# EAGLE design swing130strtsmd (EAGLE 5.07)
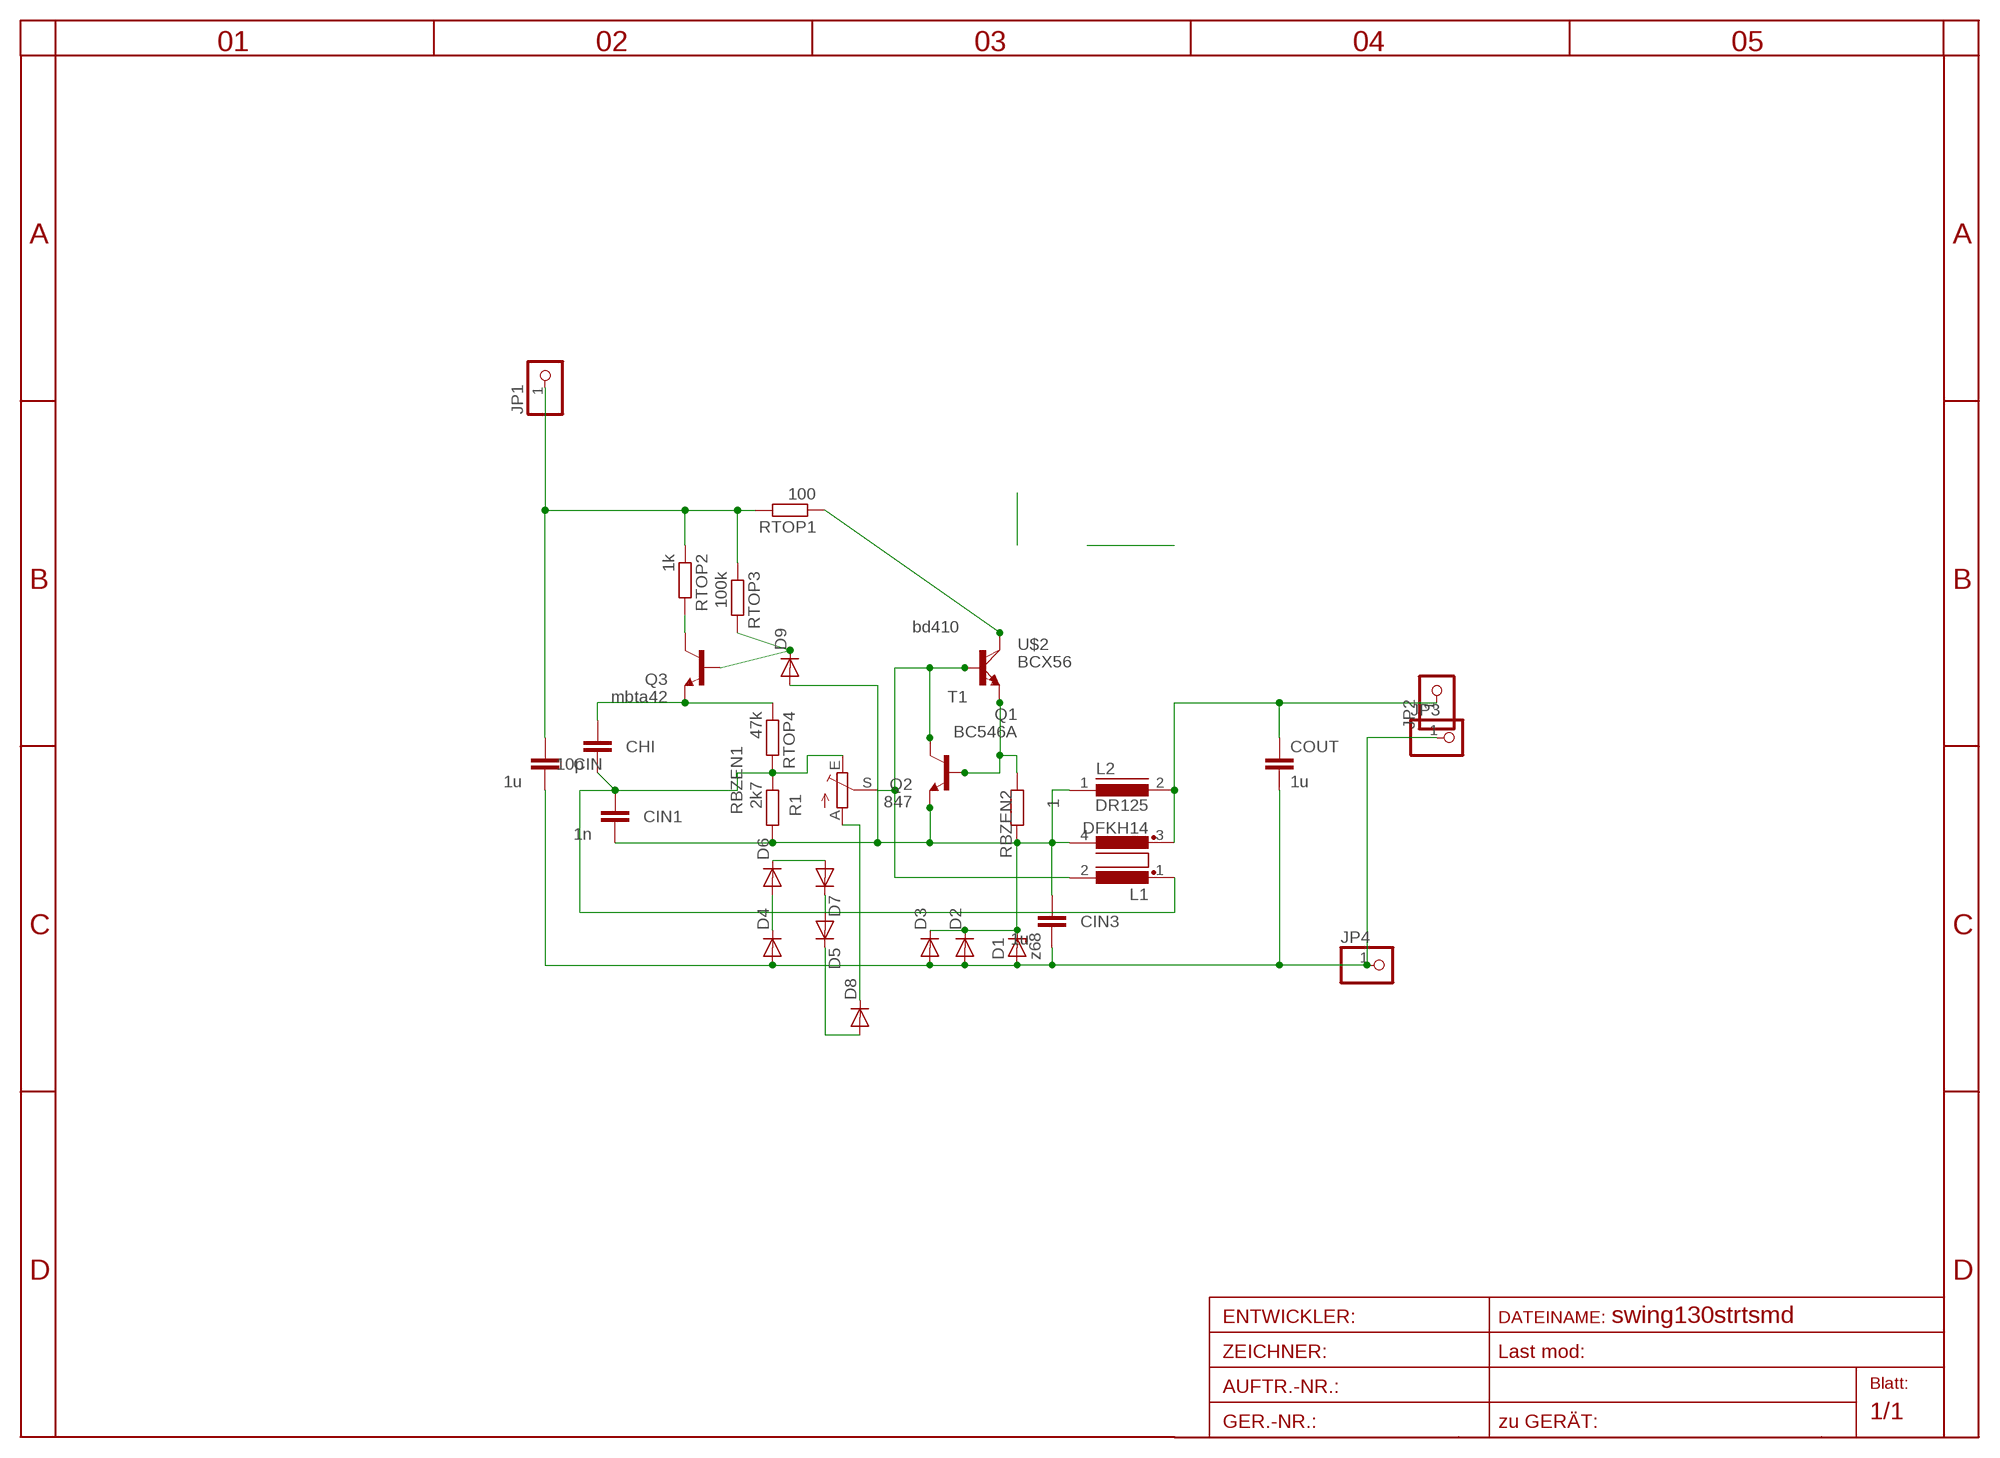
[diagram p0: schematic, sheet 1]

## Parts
CHI  10p  C-EUC0805  [C0805]
CIN  1u  C-EU025-024X044  [C025-024X044]
CIN1  1n  C-EUC0805  [C0805]
CIN3  1u  C-EU025-024X044  [C025-024X044]
COUT  1u  C-EU025_050-055X075  [C025_050-055X075]
D1  z68  ZENER-DIODESOD80C  [SOD80C]
D2  DIODE-D-5  [D-5]
D3  DIODE-SMC  [SMC]
D4  DIODE-MINIMELF  [MINIMELF]
D5  DIODE-MINIMELF  [MINIMELF]
D6  DIODE-MINIMELF  [MINIMELF]
D7  DIODE-MINIMELF  [MINIMELF]
D8  DIODE-MINIMELF  [MINIMELF]
D9  DIODE-MINIMELF  [MINIMELF]
JP1  PINHD-1X11X0.4  [1X01]
JP2  PINHD-1X11X0.4  [1X01]
JP3  PINHD-1X11X0.4  [1X01]
JP4  PINHD-1X11X0.4  [1X01]
L1  DFKH14  DFKH145MM  [ROUND1]
L2  DR125  [DR125]
Q1  BC546A  [TO92-EBC]
Q2  847  BC847ASMD  [SOT23]
Q3  mbta42  BC847ASMD  [SOT23]
R1  TRIM_EU-S64W  [S64W]
RBZEN1  2k7  R-EU_R0805  [R0805]
RBZEN2  1  R-EU_0207/10  [0207/10]
RTOP1  100  R-EU_0207/12  [0207/12]
RTOP2  1k  R-EU_R0805  [R0805]
RTOP3  100k  R-EU_R2010  [R2010]
RTOP4  47k  R-EU_R0805  [R0805]
T1  bd410  -NPN-TO126V  [TO126V]
U$2  BCX56  [SOT223]

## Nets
C: RTOP1.1 T1.2(C) U$2.2(C)
CB: L1.2 Q1.C Q2.3(C) R1.S T1.3(B) U$2.1(B)
DB: CIN1.2 CIN3.1 D1.C D2.C D3.C D9.A L1.4 L2.1 Q1.E Q2.2(E) RBZEN1.2 RBZEN2.2
EE: Q1.B Q2.1(B) RBZEN2.1 T1.1(E) U$2.3(E)
GND: CIN3.2 CIN.2 COUT.2 D1.A D2.A D3.A D4.A JP3.1 JP4.1
LIM: D9.C Q3.1(B) RTOP3.2
MID: CHI.2 CIN1.1 L1.1 R1.E RBZEN1.1 RTOP4.2
N$1: D4.C D6.A
N$2: D6.C D7.A
N$4: D5.A D7.C
N$5: D5.C D8.A
N$7: CHI.1 Q3.2(E) RTOP4.1
N$8: D8.C R1.A
N$10: Q3.3(C) RTOP2.2
OUT: COUT.1 JP2.1 L1.3 L2.2
VPLUS: CIN.1 JP1.1 RTOP1.2 RTOP2.1 RTOP3.1

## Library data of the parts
CHI CIN CIN1 CIN3 COUT = rcl:C-EU: CAPACITOR, European symbol
D1 = diode:ZENER-DIODE: Z-Diode
D2 = diode:DIODE-: DIODE
D3-D9 = diode-1:DIODE-: DIODE
JP1-JP4 = pinhead:PINHD-1X1: PIN HEADER
L1 = inductors:DFKH14: FILTER
L2 = inductors:DR125: High Power Density, High Efficiency, Shielded Inductors
Q1 = transistor-npn:BC546*: NPN Transistor
Q2 Q3 = transistor-npn:BC847*: NPN Transistor
R1 = pot-7:TRIM_EU-: POTENTIOMETER
RBZEN1 RBZEN2 RTOP1-RTOP4 = rcl:R-EU_: RESISTOR, European symbol
T1 = transistor:*-NPN-: NPN Transistror BF959 corrected 2008.03.06
U$2 = transistor-power:BCX56

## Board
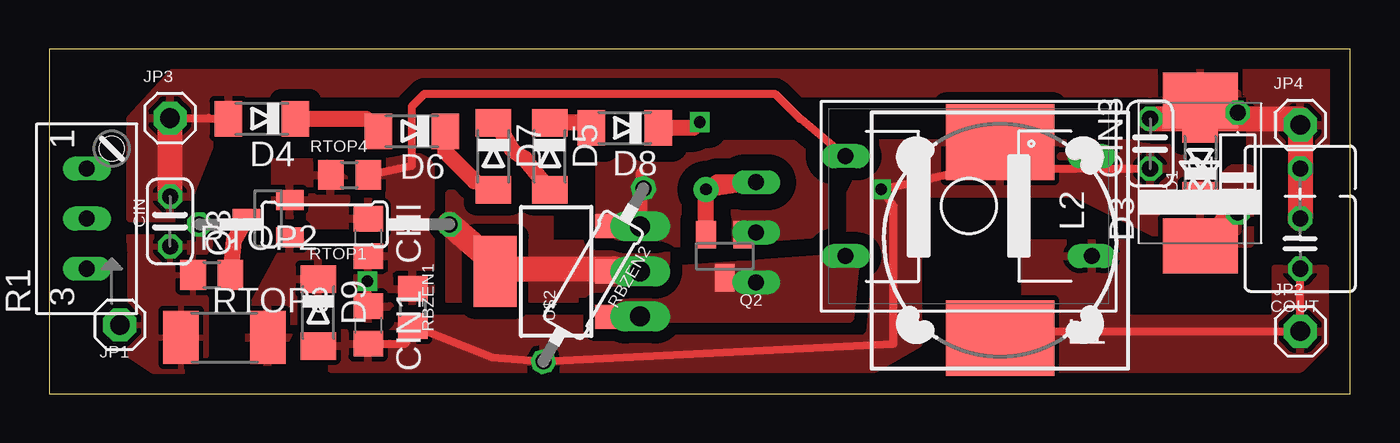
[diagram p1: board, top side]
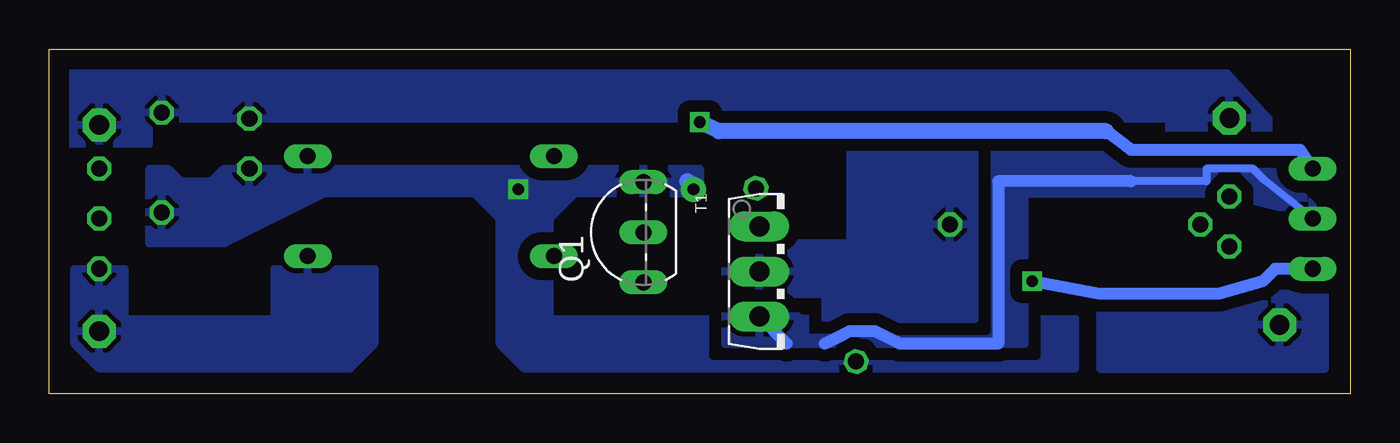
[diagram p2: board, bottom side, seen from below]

Size 66.04 x 17.5 mm. Coordinates in mm from the lower left corner, seen from the top.
Outline: 0,0 66.04,0 66.04,17.5 0,17.5 0,0
Copper layers (1*16): Top 0.035mm / dielectric 1.5mm / Bottom 0.035mm
Design rules "default *": minimum track width 10mil, minimum drill 20mil, track to track 8mil, track to pad 8mil, pad to pad 8mil, via to via 8mil, smd to smd 8mil, copper to edge 40mil, drill to drill 8mil, minimum pad ring 1mil, minimum via ring 8mil, stop-mask expansion 4mil, vias tented up to drill 0mil, thermal gap 10mil

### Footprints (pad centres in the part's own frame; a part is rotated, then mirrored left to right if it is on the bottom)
C0805 = smd 1.3 x 1.5: 1 -0.95,0; 2 0.95,0
C025-024X044 = drill 0.813 octagon: 1 -1.27,0; 2 1.27,0
C025_050-055X075 = drill 0.813 octagon: 1 -1.27,0; 2 1.27,0; 3 3.81,0
SOD80C = smd 1.4 x 1.8: A 1.7,0; C -1.7,0
D-5 = drill 0.813 octagon: A 2.54,0; C -2.54,0
SMC = smd 2.8 x 3.8: A 3.7,0; C -3.7,0
MINIMELF = smd 1.4 x 1.8: A 1.7,0; C -1.7,0
1X01 = drill 1 pad 1.676 octagon: 1 0,0
ROUND1 = drill 0.813 long: 1 6.248,-2.54; 2 6.248,2.54; 3 -6.248,2.54; 4 -6.248,-2.54
DR125 = smd 3.85 x 5.5: 1 -4.975,0; 2 4.975,0
TO92-EBC = drill 0.813 long: B 0,-1.27; C -2.54,-1.27; E 2.54,-1.27
SOT23 = smd 1 x 1.4: 1 -0.95,-1.1; 2 0.95,-1.1; 3 0,1.1
S64W = drill 0.813 long: A 2.54,1.27; E -2.54,1.27; S 0,1.27
R0805 = smd 1.3 x 1.5: 1 -0.95,0; 2 0.95,0
0207/10 = drill 0.813 octagon: 1 -5.08,0; 2 5.08,0
0207/12 = drill 0.813 octagon: 1 -6.35,0; 2 6.35,0
R2010 = smd 1.8 x 2.7: 1 -2.2,0; 2 2.2,0
TO126V = drill 1.016 long: 1 -2.286,-1.27; 2 0,-1.27; 3 2.286,-1.27
SOT223 = smd 1.219 x 2.235: 1 -2.311,-3.099; 2 0,-3.099; 3 2.311,-3.099 | smd 3.6 x 2.2: 4 0,3.099

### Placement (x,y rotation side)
CHI  16.19,7.94 270 top
CIN  6.13,8.75 90 top
CIN1  16.19,3.49 270 top
CIN3  55.88,12.7 90 top
COUT  63.5,7.62 90 top
D1  58.42,11.75 90 top
D2  60.32,11.75 90 top
D3  58.42,11.2 90 top
D4  10.79,13.97 180 top
D5  25.4,12.06 270 top
D6  18.41,13.34 180 top
D7  22.54,12.06 270 top
D8  29.21,13.5 180 top
D9  13.65,4.13 270 top
JP1  3.59,3.5 0 top
JP2  63.5,3.17 0 top
JP3  6.13,14 0 top
JP4  63.5,13.65 0 top
L1  46.67,9.53 180 top
L2  48.26,7.8 270 top
Q1  37.15,8.2 90 bottom
Q2  34.29,6.99 180 top
Q3  11.11,8.89 90 top
R1  3.17,8.89 90 top
RBZEN1  18.46,4.38 270 top
RBZEN2  27.62,6.03 240 top
RTOP1  13.97,8.6 180 top
RTOP2  8.26,6.03 0 top
RTOP3  8.89,2.86 0 top
RTOP4  15.24,11.11 0 top
T1  28.73,6.21 270 bottom
U$2  25.73,6.21 90 top

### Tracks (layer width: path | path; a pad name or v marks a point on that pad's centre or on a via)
C
  Top 0.406: 22.54,6.67 22.86,6.35 | 28.69,6.35 U$2.2 T1.2
  Top 1.27: 22.54,6.67 RTOP1.1 | 22.86,6.35 28.69,6.35
  pour Bottom (isolate 0.61): 19.05,12.7 25.4,12.7 25.4,7.62 31.75,7.62 31.75,5.08 26.67,5.08 26.67,3.81 19.05,3.81
  pour Top (isolate 0.61, rank 4, no thermals): 20.32,10.16 25.4,10.16 25.4,7.62 31.75,7.62 31.75,5.08 26.67,5.08 26.67,3.81 20.32,3.81
CB
  Bottom 0.406: R1.S 4.38,10.87 4.94,11.43 7.3,11.43 7.3,10.79 11.11,10.79
  Bottom 0.61: 26.67,2.54 25.4,3.17 24.13,3.17 22.86,2.54 17.87,2.54 17.87,10.79 11.11,10.79 | T1.3 28.62,2.54
  pour Top (isolate 0.61, rank 2, no thermals): 40.96,6.99 40.64,3.81 27.94,3.81 31.75,6.35
  pour Bottom (isolate 0.61, rank 2): 1.27,8.89 5.08,12.7 19.05,12.7 19.05,3.81 27.94,3.81 29.21,5.08 31.75,5.08 31.75,2.54 16.51,2.54 16.51,10.16 6.35,10.16
DB  (via drill 0.6, 0.6 pad 1.27)
  Top 0.406: 46.88,11.43 CIN3.1 | 46.88,11.43 L2.1 | CIN1.2 18.08,2.54 RBZEN1.2 22.48,1.84 RBZEN2.2 42.86,2.54 42.86,9.53 v42.23,10.38 46.88,11.43 | Q2.2
  Top 0.813: v33.34,10.38 Q1.E 33.92,10.74 33.34,10.16 Q2.2 | L2.1 49.55,12.77 | D2.C 59.9,9.21 D3.C
  Bottom 0.813: 33.66,10.79 33.34,10.48 v33.34,10.38
  pour Top (isolate 0.61, rank 3): 14.29,3.81 14.29,1.27 41.91,1.27 44.13,2.54 44.13,8.89 44.45,10.16 52.07,10.16 57.15,7.62 60.96,7.62 60.96,11.43 60.01,11.43 59.37,10.79 57.78,10.79 57.15,12.7 41.91,12.7 40.64,10.16 40.64,3.81
  pour Bottom (isolate 0.61, rank 3): 13.97,3.81 13.97,1.27 41.91,1.27 43.18,2.54 43.18,8.89 44.45,10.16 52.07,10.16 57.15,7.62 60.96,7.62 60.96,11.43 60.01,11.43 59.37,10.79 57.78,10.79 57.15,11.43 33.02,11.43 33.02,10.16 39.37,10.16 40.64,8.89 40.64,3.81
EE
  Top 0.406: RBZEN2.1 30.16,8.78 U$2.3 29.98,8.52 T1.1 30,11.27
  Top 0.813: Q2.1 35.76,8.09 Q1.B
  pour Top (isolate 0.813, rank 4, no thermals): 27.94,8.89 27.94,12.7 28.57,12.06 30.8,12.06 31.43,12.7 39.37,12.7 39.37,7.62 29.21,7.62
GND
  Top 0.406: 63.5,13.97 JP4.1 63.5,13.34 | 58.62,13.97 D1.A | D1.A 59.48,13.97 | D1.A 59.8,13.77 D2.A | JP3.1 8.11,14 D4.A
  Top 0.813: 58.62,13.97 58.62,15.34 D3.A
  Top 1.27: 63.5,13.34 COUT.2 | CIN.2 JP3.1 | CIN3.2 58.62,13.97 | 59.48,13.97 63.5,13.97
  pour Bottom (isolate 0.61): 4.13,13.97 7.62,17.78 66.04,17.78 66.04,12.7 60.96,12.7 60.96,13.97 9.21,13.97 9.21,12.7 4.13,12.7
  pour Top (isolate 0.61): 4.13,13.97 7.62,17.78 66.04,17.78 66.04,12.7 60.96,12.7 60.96,15.24 55.88,15.24 9.21,15.24 6.67,8.89 4.13,8.89
LIM
  pour Top (isolate 0.406): 10.16,1.91 10.16,4.13 12.38,8.26 13.97,6.35 13.65,5.08 12.38,4.76 12.38,3.49 11.43,1.59 10.48,1.59
MID  (via drill 0.6)
  Top 0.406: RTOP4.2 18.41,11.58 18.41,14.61 19.05,15.24 36.83,15.24 38.1,13.97 38.15,13.97 L1.1 | RBZEN1.1 18.2,5.71 | v16.15,5.71 16.15,4.49 CIN1.1
  Bottom 0.61: R1.E 3.81,6.35 4.45,5.71 6.67,5.08 12.75,5.08 v16.15,5.71
  pour Top (isolate 0.406, rank 4): 16.83,11.75 18.73,12.06 19.37,11.75 19.37,5.08 15.88,3.49 15.56,6.67 17.14,6.67
N$1
  Top 0.406: 16.08,13.97 D6.A
  Top 0.813: D4.C 16.08,13.97
N$2
  Top 0.406: 21.59,10.79 22.43,10.79 D7.A
  Top 0.813: D6.C 20.11,12.27 21.59,10.79
N$4
  Top 0.406: D7.C 22.54,13.97
  Top 0.813: 22.54,13.97 23.5,12.38 24.13,11.95 D5.A
N$5
  Top 0.406: D8.A 27.4,13.77
  Top 0.813: 27.4,13.77 D5.C
N$7
  pour Top (isolate 0.406): 13.97,11.75 11.43,11.75 11.43,8.57 16.51,8.57 16.19,9.84 15.56,10.48
N$8  (via drill 0.6)
  Top 0.406: v33.02,13.8 32.7,13.5
  Top 0.813: 32.7,13.5 D8.C
  Bottom 0.61: R1.A 2.54,12.38 11.11,12.38 12.38,13.34
  Bottom 0.813: 12.38,13.34 32.07,13.34 v33.02,13.8
N$10
  Top 0.813: Q3.3 9.38,7.79 RTOP2.2
OUT
  Top 0.406: 50.8,3.17 47.41,2.86 L2.2 | 50.8,3.17 JP2.1 COUT.1 | 46.89,3.28 50.8,3.17
  pour Top (isolate 0.61, rank 3): 49.53,7.62 49.53,2.54 50.8,1.27 63.5,1.27 64.77,2.54 64.77,6.35 62.23,6.35 62.23,3.81 54.61,3.81 54.61,7.62
  pour Bottom (isolate 0.61, rank 3): 49.53,6.35 49.53,2.54 50.8,1.27 63.5,1.27 64.77,2.54 64.77,6.35 62.23,6.35 62.23,3.81 54.61,3.81 54.61,6.35
VPLUS
  pour Top (isolate 0.61, rank 2): 8.26,8.89 7.94,5.08 7.94,1.91 6.03,0.64 4.13,1.91 4.13,6.99 4.07,8.26 5.34,9.21
  pour Bottom (isolate 0.61, rank 2): 1.27,1.27 1.27,5.08 12.7,5.08 12.7,1.27

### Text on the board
tStop: MICHAEL5.net
bStop: MICHAEL5.net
